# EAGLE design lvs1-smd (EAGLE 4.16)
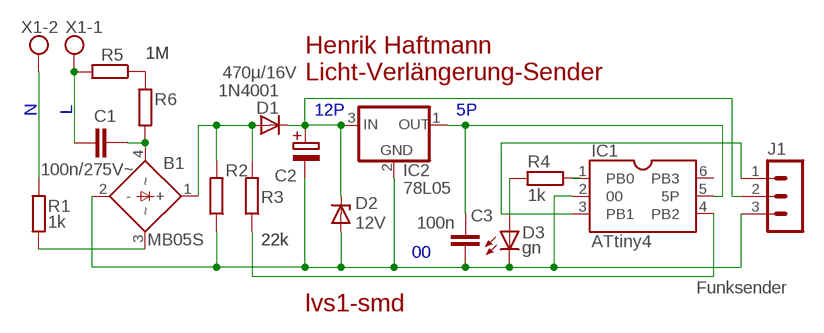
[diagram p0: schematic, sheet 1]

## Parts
B1  MB05S  DBM  [DBS]
C1  100n/275V~  C15  [C150-084X183]
C2  470µ/16V  E02-10  [E02-10]
C3  100n  C0603  [0603]
D1  1N4001  D  [MINIMELF]
D2  12V  DZ1206  [1206]
D3  gn  LED0603  [0603]
IC1  ATtiny4  TN4  [SOT23-6]
IC2  78L05  78XX89  [SOT89]
J1  Funksender  MA03-1  [MA03-1]
R1  1k  R02  [R02]
R2  22k  R0603  [0603]
R3  22k  R0603  [0603]
R4  1k  R0603  [0603]
R5  1M  R1206  [1206]
R6  1M  R1206  [1206]
X1  W237-02P  [W237-132]

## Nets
00: B1.2(-) C2.- C3.2 D2.1(A) D3.2(K) IC1.2 IC2.2(GND) J1.3 R2.1
5P: C3.1 IC1.5(5P) IC2.1(OUT)
12P: C2.+ D1.K D2.2(K) IC2.3(IN) J1.2
!ZC: IC1.4(PB2) R3.1
L: C1.1 R5.2 X1.1
N: R1.2 X1.2
N$1: B1.4(~) C1.2 R6.2
N$2: IC1.3(PB1) J1.1
N$3: B1.1(+) D1.A R2.2 R3.2
N$4: B1.3(~) R1.1
N$5: IC1.1(PB0) R4.1
N$6: D3.1(A) R4.2
N$7: R5.1 R6.1
Unconnected: IC1.6(PB3)

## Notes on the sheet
- Henrik Haftmann
- Licht-Verlängerung-Sender

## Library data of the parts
B1 = fu:DB: Gleichrichterbrücke 1-phasig Typliste TypSpannungStromGehäuse MB05S..MB10S50..1000 V0,5 AMBS, e=2,5mm
C1 C3 = fu:C: Kondensator
C2 = fu:E: Elektrolytkondensator, gepolt
D1 = fu:D: Diode
D2 = fu:DZ: Z-Diode
D3 = fu:LED: Leuchtdiode
IC1 = fu:TN4: AVR-Mikrocontroller TypFlashRAMADCSignatur ATtiny451232nein0x1E 0x8F 0x0A ATtiny551232ja0x1E 0x8F 0x09 ATtiny9102432nein0x1E 0x90 0x08 ATtiny10102432ja0x1E 0x90 0x03
IC2 = fu:78XX: Spannungsregler positiv (78xx) oder negativ (79xx)
J1 = con-lstb:MA03-1: PIN HEADER
R1-R6 = fu:R: Widerstand
X1 = con-wago-508:W237-02P: WAGO SREW CLAMP

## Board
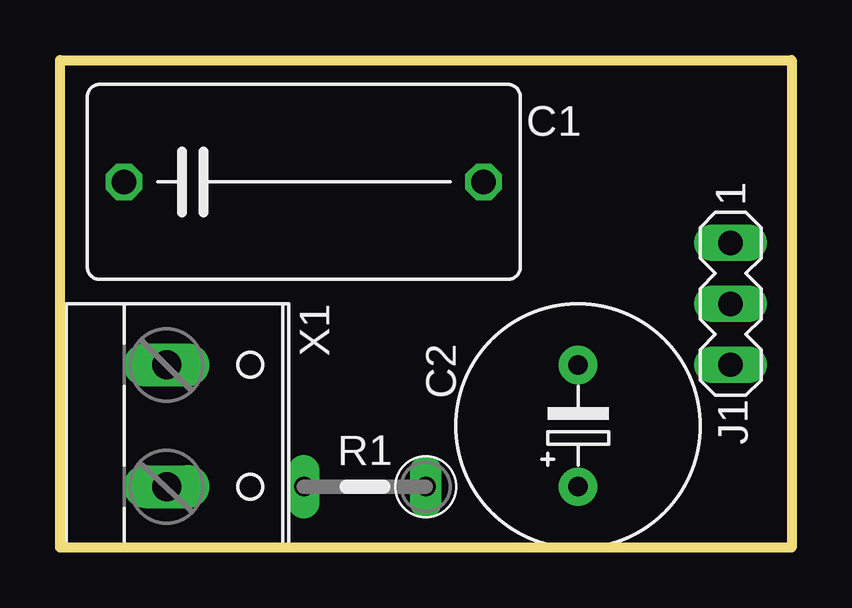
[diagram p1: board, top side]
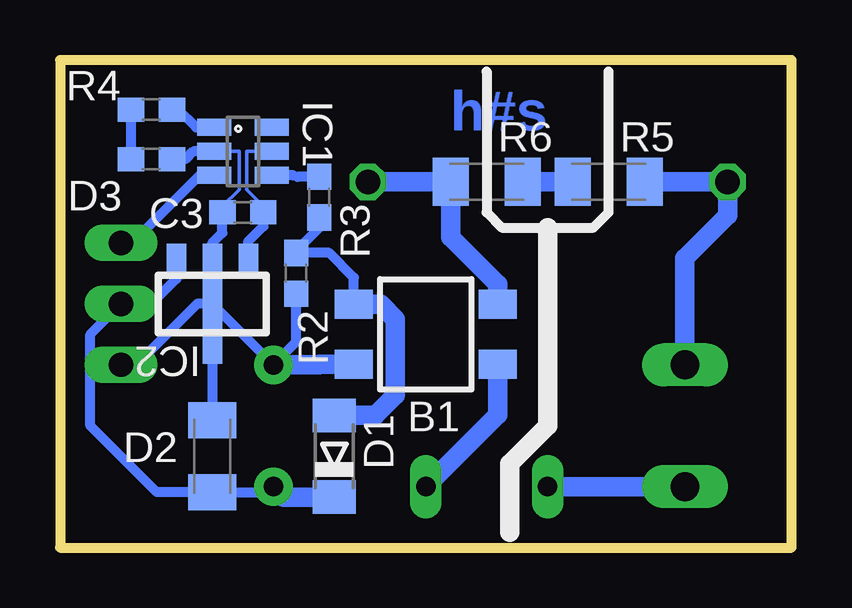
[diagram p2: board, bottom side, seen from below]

Size 30.48 x 20.32 mm. Coordinates in mm from the lower left corner, seen from the top.
Outline: 0,20.32 30.48,20.32 30.48,0 0,0 0,20.32
Copper layers 16: Bottom 0.035mm
Design rules "default": minimum track width 0.15mm, minimum drill 0.6mm, track to track 0.15mm, track to pad 0.15mm, pad to pad 0.15mm, via to via 0.15mm, smd to smd 0mil, copper to edge 0.5mm, drill to drill 8mil, minimum pad ring 10mil, minimum via ring 8mil, stop-mask expansion 4mil, vias tented up to drill 0mil, thermal gap 10mil

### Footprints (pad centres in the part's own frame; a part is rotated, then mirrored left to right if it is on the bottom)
DBS = smd 1.2 x 1.6: 1 -1.25,-3; 2 1.25,-3; 3 1.25,3; 4 -1.25,3
C150-084X183 = drill 1.016 octagon: 1 -7.493,0; 2 7.493,0
E02-10 = drill 0.813 pad 1.6 round: + -2.54,0; - 2.54,0
0603 = smd 1.1 x 1: 1 -0.85,0; 2 0.85,0
MINIMELF = smd 1.4 x 1.8: A 1.7,0; K -1.7,0
1206 = smd 1.5 x 2: 1 -1.5,0; 2 1.5,0
SOT23-6 = smd 0.711 x 1.422: 1 -1,-1.2; 2 0,-1.2; 3 1,-1.2; 4 1,1.2; 5 0,1.2; 6 -1,1.2
SOT89 = smd 0.8 x 1.4: 1 -1.5,-1.8; 3 1.5,-1.8 | smd 0.8 x 5: 2 0,0
MA03-1 = drill 1.016 long: 1 -2.54,0; 2 0,0; 3 2.54,0
R02 = drill 0.813 long: 1 -2.54,0; 2 2.54,0
W237-132 = drill 1.194 long: 1 -2.54,-0.635; 2 2.54,-0.635

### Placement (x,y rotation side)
B1  15.24,8.89 270 bottom
C1  10.16,15.24 0 top
C2  21.59,5.08 90 top
C3  22.86,13.97 180 bottom
D1  19.05,3.81 90 bottom
D2  24.13,3.81 270 bottom
D3  26.67,16.19 0 bottom
IC1  22.86,16.51 270 bottom
IC2  24.13,10.16 180 bottom
J1  27.94,10.16 270 top
R1  12.7,2.54 180 top
R2  20.64,11.43 90 bottom
R3  19.68,14.61 270 bottom
R4  26.67,18.26 180 bottom
R5  7.62,15.24 0 bottom
R6  12.7,15.24 180 bottom
X1  5.08,5.08 270 top

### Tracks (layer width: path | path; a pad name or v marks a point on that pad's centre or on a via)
00
  Bottom 0.15: IC1.2 23.02,16.51 23.02,14.92 23.71,14.23 C3.2
  Bottom 0.406: D3.2 25.24,16.19 24.92,16.51 IC1.2 | C3.2 23.71,13.12 24.13,12.7 IC2.2 | J1.3 27.3,7.62 24.77,10.16 IC2.2 | R2.1 20.64,8.57 C2.- IC2.2 | 19.66,7.64 19.68,7.62 | IC2.2 D2.1
  Bottom 0.813: B1.2 19.66,7.64 | 19.68,7.62 C2.-
5P
  Bottom 0.15: IC1.5 22.7,16.51 22.7,14.92 22.01,14.23 C3.1
  Bottom 0.406: C3.1 22.01,13.39 22.63,12.77 IC2.1
12P
  Bottom 0.406: IC2.3 25.63,11.2 26.67,10.16 J1.2 29.21,8.89 29.21,5.08 26.44,2.31 D2.2 21.82,2.31 C2.+
  Bottom 0.813: D1.K 21.16,2.11 C2.+
!ZC
  Bottom 0.15: 20.58,15.46 20.64,15.4 20.75,15.51
  Bottom 0.406: R3.1 20.58,15.46 | 20.75,15.51 IC1.4
L
  Bottom 0.15: R5.2 6.35,15.24
  Bottom 0.813: R5.2 C1.1 2.67,13.84 4.45,12.06 X1.1
N
  Bottom 0.813: X1.2 R1.2
N$1
  Bottom 0.15: C1.2 17.78,15.24
  Bottom 0.813: C1.2 R6.2 14.2,12.93 12.24,10.97 B1.4
N$2
  Bottom 0.406: IC1.3 24.65,15.51 | 24.65,15.51 24.61,15.56 | 24.65,15.51 27.46,12.7 J1.1
N$3
  Bottom 0.406: R3.2 19.68,13.34 20.64,12.38 R2.2 19.27,12.28 18.24,11.26 B1.1
  Bottom 0.813: B1.1 17.12,10.14 16.51,9.53 16.51,6.35 17.35,5.51 D1.A
N$4
  Bottom 0.813: B1.3 12.24,5.54 R1.1
N$5
  Bottom 0.406: IC1.1 24.81,17.51 25.56,18.26 R4.1
N$6
  Bottom 0.406: D3.1 R4.2
N$7
  Bottom 0.15: R6.1 11.43,15.24
  Bottom 0.813: R5.1 R6.1

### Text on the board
Bottom: h#s
Measures: 20,32 = 0.8" | 30,48 = 1.2"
